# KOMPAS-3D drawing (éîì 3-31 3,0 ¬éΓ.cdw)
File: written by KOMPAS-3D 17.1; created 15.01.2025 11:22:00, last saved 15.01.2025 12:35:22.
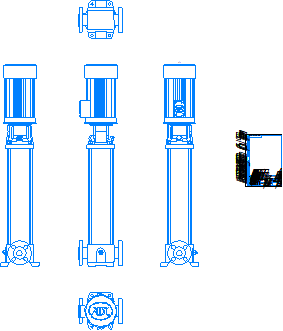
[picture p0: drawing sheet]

Sheet 1: A4, portrait

Title block, sheet 1: name: ВМН 3-31 3,0 кВт; designation: ВМН 3-31 3,0 кВт; material: Сталь 10  ГОСТ 1050-2013; mass: 68,16; sheets: 1; sheet format: A4; stored path: \\adlc.lan\data\АДЛ_ПКД\3D-модели\ADL production\Насосы ГРАНПАМП\Насосы ВМН\ВМН3\KOMPAS 3D\ВМН 3-31 3,0 кВт.cdw

Views: Проекционный вид 2, Проекционный вид 3, Проекционный вид 4, Проекционный вид 5
Referenced files in \\adlc.lan\data\АДЛ_ПКД\3D-модели\ADL production\Насосы ГРАНПАМП\Насосы ВМН\ВМН3\KOMPAS 3D\: ВМН 3-31 3,0 кВт.m3d
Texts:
  Andrey
  АДЛ
Dimensions and other numbers on the sheet: 1:1; 1; 68,16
